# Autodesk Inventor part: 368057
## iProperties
Created: 2006-06
Part Number: 368057
Document SubType Name: Modeling
Designer: I.Baliuc
Material: 8.8 vz
Description: Sperrzahnmutter
Density: 7.85 g/cm^3
Mass: 4.08533 g
Surface Area: 5.38271 cm^2
Volume: 0.520424 cm^3
Abmessung: M6
Author: T.Messerschmitt
Revision Number: 368057
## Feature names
1. Basis1
